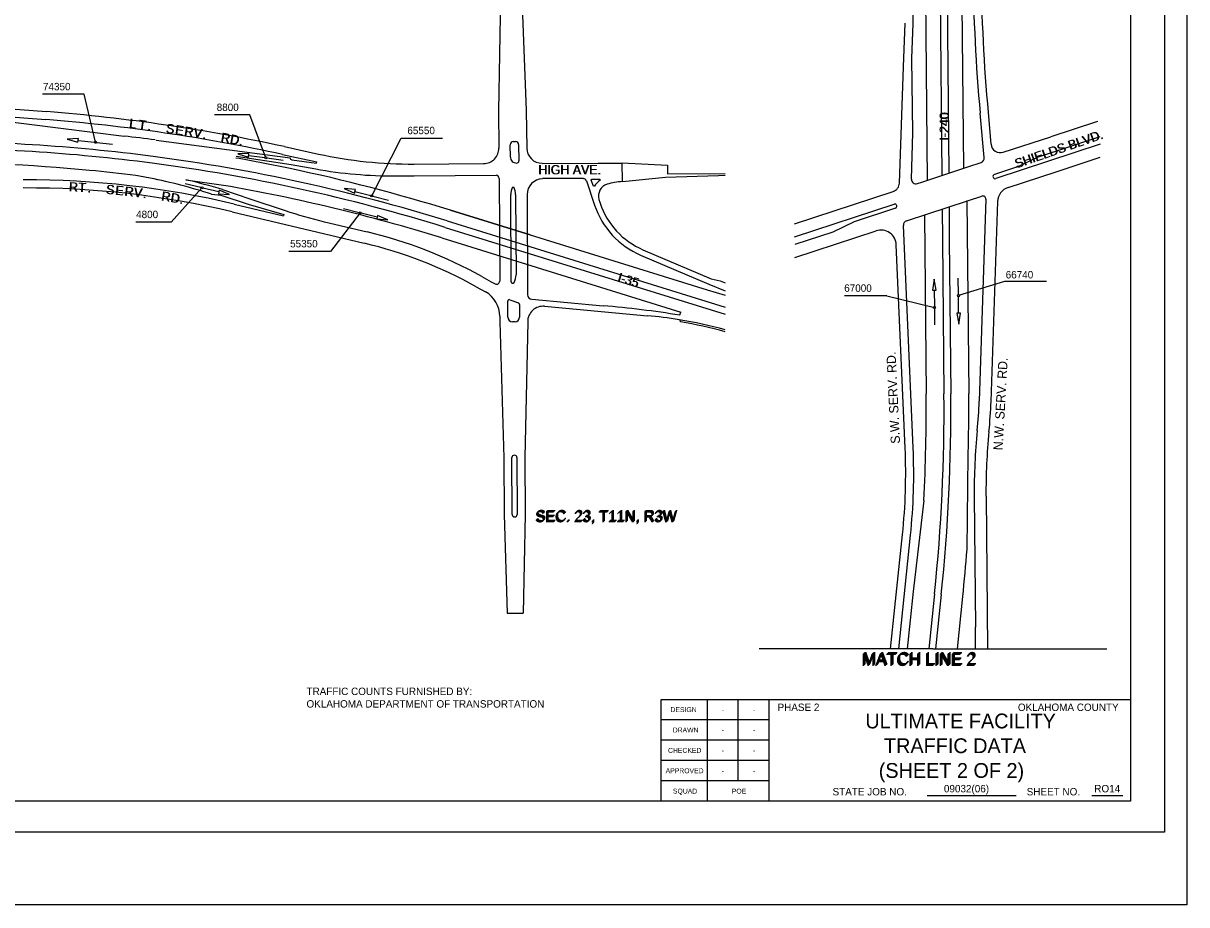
# Model space of a CAD drawing. Extents: x 143344 to 150544, y -2153266 to -2148466.
# Drawn here: x 146776 to 150544, y -2153266 to -2150410 of the extents above; entities that cross this region are included whole.
import ezdxf

# ---------------------------------------------------------------- set-up
doc = ezdxf.new("R2010")
doc.units = 0
for name, color, linetype in [('4', 7, 'Continuous'), ('5', 7, 'Continuous'), ('6', 7, 'Continuous'), ('EXIST', 7, 'Continuous'), ('EXPAV', 7, 'Continuous'), ('PH1a-PR-I240', 7, 'Continuous'), ('PH1a-PR-ServRd', 7, 'Continuous'), ('PROP', 7, 'Continuous'), ('SHT_Plot_Shape_Full', 7, 'Continuous'), ('SHT_Plot_Shape_Half', 7, 'Continuous'), ('SHT_Sheet_Border', 7, 'Continuous'), ('SHT_Standard_Sheet_Lines', 7, 'Continuous'), ('SHT_Standard_Sheet_Txt', 7, 'Continuous'), ('T', 7, 'Continuous')]:
    doc.layers.add(name, color=color, linetype=linetype)

# ---------------------------------------------------------------- blocks, each defined once
blk = doc.blocks.new('ARR')
at = {"layer": '6'}
for p, q in [((134.5, 0), (0, 0)), ((285.8, 0), (151.3, 0))]:
    blk.add_line(p, q, dxfattribs=at)
blk.add_lwpolyline([(285.8, 15.2), (285.8, -15.2), (377.2, 0)], close=True, dxfattribs=at)
blk.add_circle((142.9, 0), 8.42, dxfattribs=at)

msp = doc.modelspace()

# ---------------------------------------------------------------- linework, layer by layer
at = {"layer": '4'}
for q in [(149159.4, -2152436.2), (150285.6, -2152436.2)]:
    msp.add_line((149722.5, -2152436.2), q, dxfattribs=at)
at = {"layer": '6'}
for p, q in [((146972.9, -2150640.1), (146838, -2150640.1)), ((147009.6, -2150795.6), (146972.9, -2150640.1)), ((146972.9, -2150640.1), (146972.9, -2150640.1)), ((147509.3, -2150707.1), (147395.5, -2150707.1)), ((147561.9, -2150845.4), (147509.3, -2150707.1)), ((147509.3, -2150707.1), (147509.3, -2150707.1)), ((147904.5, -2150968.9), (148000.3, -2150782.2)), ((148000.3, -2150782.2), (148000.3, -2150782.2)), ((148000.3, -2150782.2), (148133.6, -2150782.2)), ((147354.8, -2150943.2), (147254.8, -2151054.2)), ((147867.5, -2151024.5), (147771.5, -2151148.9)), ((147254.8, -2151054.2), (147141, -2151054.2)), ((147254.8, -2151054.2), (147254.8, -2151054.2)), ((147771.5, -2151148.9), (147635.8, -2151148.9)), ((147771.5, -2151148.9), (147771.5, -2151148.9)), ((149954.3, -2151246.4), (149804.9, -2151292.4)), ((150090.5, -2151246.4), (149954.3, -2151246.4)), ((149572.6, -2151292.8), (149436.4, -2151292.8)), ((149572.6, -2151292.8), (149726.9, -2151331.1))]:
    msp.add_line(p, q, dxfattribs=at)
at = {"layer": 'EXIST'}
for p, q in [((146656.1, -2150681), (146851.2, -2150696.3)), ((146631.6, -2150715.7), (147102.9, -2150775.7)), ((146653.9, -2150706.9), (146849.2, -2150722.2))]:
    msp.add_line(p, q, dxfattribs=at)
for centre, radius, start, end in [((146449, -2156533.3), 5794.6, 82.52117, 83.52117), ((146449, -2156533.3), 5740.6, 82.52117, 90.35541), ((146449, -2156533.3), 5718.6, 82.5212, 90.3554), ((146449, -2156533.3), 5672.6, 84.5212, 90.3555), ((146449, -2156533.3), 5672.6, 82.9934, 84.5212), ((146809.2, -2152777.8), 1903.9, 78.5556, 79.965)]:
    msp.add_arc(centre, radius, start, end, dxfattribs=at)
at = {"layer": 'EXPAV'}
for p, q in [((148329.1, -2149864.1), (148315.2, -2150693.8)), ((148374.1, -2149923), (148405.2, -2150692.7)), ((148315.2, -2150693.8), (148316.6, -2150814.1)), ((148405.2, -2150692.7), (148406.6, -2150814.1)), ((150255.6, -2150728), (150104.5, -2150777.6)), ((149949.7, -2150827.6), (150104.5, -2150777.6)), ((150060.9, -2150843.5), (150264.2, -2150776.8)), ((147206.7, -2150788.5), (147640.3, -2150845.7)), ((147621.6, -2150809.7), (147732.3, -2150833.7)), ((148353.9, -2150843.3), (148353.4, -2150803.3)), ((148363.3, -2150793.2), (148370.3, -2150793.1)), ((148380.4, -2150803), (148381.1, -2150856)), ((150264.2, -2150802.1), (149925.9, -2150913.1)), ((147465.5, -2150840.7), (147643.5, -2150867.3)), ((147616.1, -2150835.1), (147726.3, -2150859)), ((147645.4, -2150852.4), (147725.6, -2150863)), ((149992.8, -2150876.4), (150060.9, -2150843.5)), ((150121.8, -2150890.9), (150264.1, -2150844.2)), ((147643.5, -2150867.3), (147723.1, -2150881.8)), ((147725.6, -2150863), (147726.3, -2150859)), ((148042.1, -2150866), (148266.9, -2150864.7)), ((148456.9, -2150864.7), (148637.3, -2150863.6)), ((148637.3, -2150863.6), (148716.3, -2150863.1)), ((148715.1, -2150861.9), (148715.5, -2150923.1)), ((148716.3, -2150861.9), (148862.3, -2150869.5)), ((148862.3, -2150869.5), (148862.5, -2150897.6)), ((149992.8, -2150876.4), (149921.5, -2150899.8)), ((149966.1, -2150942), (150121.8, -2150890.9)), ((147302.2, -2150917.2), (147424.4, -2150935)), ((147302.2, -2150917.2), (147424.4, -2150935)), ((147981.6, -2150904.4), (148042.4, -2150904)), ((148042.4, -2150904), (148307.5, -2150902.5)), ((148317.6, -2150912.4), (148319.1, -2151245.3)), ((148590.6, -2150912.5), (148457.5, -2150913.3)), ((148600.1, -2150920.5), (148626.4, -2150999.1)), ((148615.2, -2150918.3), (148617, -2150915.5)), ((148622.6, -2150937.3), (148615.2, -2150918.3)), ((148617, -2150915.5), (148643.4, -2150914.7)), ((148643.4, -2150914.7), (148644.6, -2150918.4)), ((148716.7, -2150923.1), (148856.6, -2150908.2)), ((148856.6, -2150908.2), (149027.6, -2150902.9)), ((148862.5, -2150897.6), (149048.9, -2150896.4)), ((149027.6, -2150902.9), (149048.9, -2150902.3)), ((147385.3, -2150963.2), (147415.6, -2150966.8)), ((147415.6, -2150966.8), (147504.1, -2150996.4)), ((147421.7, -2150948.8), (147510.1, -2150978.4)), ((148356, -2151240), (148354.8, -2150965)), ((148360.9, -2150940.8), (148364.4, -2150940.7)), ((148370.8, -2150964.9), (148372, -2151224.9)), ((148407.8, -2150964.8), (148409.3, -2151289.2)), ((148626.2, -2150937.6), (148622.6, -2150937.3)), ((149273.9, -2151059.8), (149593.2, -2150955)), ((147458.7, -2150995.6), (147618.3, -2151033.6)), ((147504.1, -2150996.4), (147619.4, -2151029.7)), ((147510.1, -2150978.4), (147623.8, -2151016.4)), ((149274.3, -2151101.8), (149596.3, -2150996.1)), ((147452.7, -2151020.9), (147880.6, -2151122.7)), ((147619.4, -2151029.7), (147618.3, -2151033.6)), ((148417.5, -2151095.8), (148159.8, -2151015.9)), ((148159.8, -2151015.9), (148417.5, -2151095.8)), ((149600.7, -2151009.4), (149466.7, -2151053.4)), ((147751.1, -2151052.8), (147889.4, -2151085.7)), ((148142.6, -2151071.3), (149048.9, -2151352.3)), ((148149.2, -2151050.2), (149048.9, -2151329.2)), ((149274.9, -2151169), (149538.1, -2151082.6)), ((149466.7, -2151053.4), (149398.6, -2151086.3)), ((148132, -2151105.6), (148905.4, -2151345.4)), ((148417.5, -2151095.8), (148990.6, -2151273.5)), ((149398.6, -2151086.3), (149274.5, -2151127)), ((148782.9, -2151143.5), (149003.7, -2151238.2)), ((148775.4, -2151160.9), (148996.2, -2151255.6)), ((148261.2, -2151230.2), (148291.8, -2151247.2)), ((148242.7, -2151263.4), (148273.4, -2151280.4)), ((148291.8, -2151247.2), (148304.2, -2151254.1)), ((148356.1, -2151247.4), (148356, -2151240)), ((148996.2, -2151255.6), (149048.9, -2151276.4)), ((149003.7, -2151238.2), (149033, -2151244.3)), ((149033, -2151244.3), (149048.9, -2151251.1)), ((148352.1, -2151305.6), (148380.2, -2151316.2)), ((148422.9, -2151304), (148654.1, -2151325.2)), ((148990.6, -2151273.5), (149048.9, -2151291)), ((148345.6, -2151362.2), (148345.4, -2151310.3)), ((148383.4, -2151320.8), (148383.6, -2151362)), ((148464.2, -2151326.9), (148797.7, -2151357.4)), ((148902.4, -2151355), (148905.4, -2151345.4)), ((148319.6, -2151358.7), (148319.7, -2151377.3)), ((148319.7, -2151377.3), (148332.7, -2151817.3)), ((148368.7, -2151377.1), (148360.7, -2151377.1)), ((148409.7, -2151376.9), (148400.7, -2151816.9)), ((148332.7, -2151817.3), (148333.5, -2152001.4)), ((148359.5, -2152001.3), (148358.7, -2151817.1)), ((148374.7, -2151817.1), (148375.5, -2152001.2)), ((148400.7, -2151816.9), (148401.5, -2152001.1)), ((148333.5, -2152001.4), (148342.9, -2152321.4)), ((148401.5, -2152001.1), (148394.9, -2152321.1)), ((148342.9, -2152321.4), (148394.9, -2152321.1))]:
    msp.add_line(p, q, dxfattribs=at)
for centre, radius, start, end in [((146402.4, -2156421.3), 5742.6, 77.74204, 85.51732), ((146402.4, -2156421.3), 5716.6, 77.742, 85.5173), ((148266.6, -2150814.7), 50, 270.3443, 0.672), ((148363.4, -2150803.2), 10, 90.672, 180.672), ((148370.4, -2150803.1), 10, 0.672, 90.672), ((148456.6, -2150813.5), 50, 180.672, 270.3596), ((146449, -2156533.3), 5740.6, 72.77283, 82.52117), ((146449, -2156533.3), 5776.6, 78.09426, 79.87617), ((147646.2, -2150846.4), 6, 172.4865, 262.4865), ((148033.6, -2149446.7), 1419.4, 257.742, 270.3443), ((148373.9, -2150843), 20, 180.672, 270.672), ((148374.1, -2150856), 7, 270.672, 0.672), ((146449, -2156533.3), 5718.6, 72.7728, 82.5212), ((146449, -2156533.3), 5776.6, 72.77283, 78.09426), ((147973.2, -2149511.7), 1392.7, 259.6534, 270.3443), ((146793.1, -2153795.4), 2877.8, 76.627, 90.3443), ((146809.2, -2152777.8), 1903.9, 72.3873, 78.5556), ((146929, -2152569), 1693.5, 73.0874, 77.2684), ((148307.6, -2150912.5), 10, 0.2591, 90.3443), ((148457.8, -2150964.5), 50, 90.3596, 180.2591), ((148590.6, -2150923.7), 10, 18.5091, 90.3596), ((148679.1, -2150969.8), 62, 123.9003, 148.6868), ((148679.1, -2150969.8), 40, 107.9501, 195.4962), ((148722.3, -2151103), 180, 91.7917, 107.9501), ((149923.7, -2150906.5), 7, 108.1765, 288.1765), ((146793.1, -2153795.4), 2851.8, 76.627, 90.3443), ((146449, -2156533.3), 5682.6, 72.7728, 80.1169), ((148404.8, -2150964.8), 50, 151.3041, 180.2591), ((148320.8, -2150965.1), 50, 0.2591, 29.2142), ((148881.5, -2150913.7), 269, 198.5091, 246.7728), ((148881.5, -2150913.7), 250, 195.4962, 198.5091), ((148881.5, -2150913.7), 250, 198.5091, 246.7728), ((149598.5, -2151002.7), 7, 288.1765, 108.1765), ((148092.5, -2149616.6), 1476.3, 251.4873, 256.627), ((147552.3, -2152503.6), 1457.4, 60.8964, 76.627), ((147552.3, -2152503.6), 1419.4, 60.8964, 76.627), ((148322, -2151225.1), 50, 330.3327, 0.2591), ((148309.1, -2151245.4), 10, 240.8964, 0.2591), ((148309.1, -2151245.4), 10, 240.8964, 0.2591), ((148361.1, -2151247.4), 5, 180.2591, 330.3327), ((148229.6, -2151359.1), 90, 0.2591, 60.8964), ((148229.6, -2151359.1), 90, 0.2591, 60.8964), ((148350.4, -2151310.3), 5, 69.3317, 180.2591), ((148424.3, -2151289.1), 15, 180.2591, 264.7728), ((148378.4, -2151320.9), 5, 0.2591, 69.3317), ((148459.7, -2151376.7), 50, 84.7728, 180.2591), ((148354.6, -2154789.9), 3477.7, 80.9383, 85.058), ((148360.6, -2151362.1), 15, 180.2591, 270.2591), ((148368.6, -2151362.1), 15, 270.2591, 0.2591), ((148667.2, -2152783.8), 1432.4, 80.6518, 84.7728), ((148667.2, -2152783.8), 1432.4, 74.5431, 80.6518), ((148898.9, -2151376.4), 6, 350.5306, 80.6518), ((148667.2, -2152783.8), 1426.4, 74.4765, 80.4108), ((148366.7, -2151817.1), 8, 0.2591, 180.2591), ((148367.5, -2152001.2), 8, 180.2591, 0.2591)]:
    msp.add_arc(centre, radius, start, end, dxfattribs=at)
at = {"layer": 'PH1a-PR-I240'}
for p, q in [((149739.6, -2149656.7), (149751.4, -2150903)), ((149764.4, -2149956.5), (149773.3, -2150895.8)), ((149695.4, -2150053.8), (149703.6, -2150918.9)), ((149816.2, -2150349.3), (149821.2, -2150879.9))]:
    msp.add_line(p, q, dxfattribs=at)
at = {"layer": 'PH1a-PR-ServRd'}
for p, q in [((149627.1, -2150551.3), (149632, -2150410)), ((149654, -2150524.4), (149658, -2150410.9)), ((149613.9, -2150927.7), (149627.1, -2150551.3)), ((149657.6, -2150764.7), (149654, -2150524.4)), ((149888.2, -2150845.3), (149875.2, -2150701.7)), ((149901.1, -2150699.4), (149910.4, -2150801.8)), ((149652.4, -2150914.6), (149657.6, -2150764.7)), ((149686.7, -2150924.5), (149838.4, -2150874.1)), ((149838.4, -2150874.1), (149878.1, -2150860.8)), ((149672.1, -2150929.3), (149686.7, -2150924.5))]:
    msp.add_line(p, q, dxfattribs=at)
for centre, radius, start, end in [((145827.6, -2150277.4), 3832.7, 358.0035, 0.5432), ((155607.4, -2150183.4), 5755.6, 180.54316, 185.16665), ((155607.4, -2150183.4), 5729.6, 180.54316, 185.16665), ((149940.3, -2150799.1), 30, 185.1667, 288.3841), ((149873.3, -2150846.6), 15, 288.5888, 5.1667), ((149584, -2150926.6), 30, 287.9834, 358.0035), ((149667.4, -2150915.1), 15, 178.0035, 288.1765)]:
    msp.add_arc(centre, radius, start, end, dxfattribs=at)
at = {"layer": 'PROP'}
for p, q in [((149837.9, -2150984.1), (149880.8, -2150970)), ((149637.2, -2151050), (149837.9, -2150984.1)), ((149774.4, -2151005), (149775.4, -2151110.1)), ((149832.2, -2150984.2), (149838.1, -2151609.5)), ((149893.9, -2150979.9), (149872.4, -2151633.8)), ((149931.7, -2150987.9), (149910.4, -2151635)), ((149694.6, -2151031.2), (149700.1, -2151610.8)), ((149752.4, -2151012.2), (149753.4, -2151110.3)), ((149658.3, -2151785.6), (149626.9, -2151064.9)), ((149753.4, -2151110.3), (149758.1, -2151610.3)), ((149775.4, -2151110.1), (149780.1, -2151610.1)), ((149632.3, -2151786.7), (149603.6, -2151127.9)), ((149833, -2152113.6), (149836.6, -2151809.7)), ((149856.3, -2151942.2), (149860.3, -2152366.4)), ((149894.3, -2151941.8), (149898.9, -2152436.2)), ((149692.9, -2151956.1), (149657.9, -2152250.5)), ((149585.2, -2152436.2), (149623.8, -2152066.1)), ((149611.4, -2152436.2), (149649.7, -2152068.8)), ((149657.9, -2152250.5), (149638.5, -2152436.2)), ((149727.5, -2152257.9), (149708.9, -2152436.2)), ((149749.4, -2152260.1), (149731, -2152436.2)), ((149801.4, -2152436.2), (149819, -2152267.4))]:
    msp.add_line(p, q, dxfattribs=at)
for centre, radius, start, end in [((149883.9, -2150979.5), 10, 358.1141, 108.1765), ((149981.6, -2150989.5), 50, 108.1324, 178.1141), ((149553.7, -2151130.1), 50, 2.4929, 108.1765), ((149641.9, -2151064.3), 15, 108.1765, 182.4929), ((144039.8, -2151664.5), 5718.6, 354.0443, 0.5432), ((144039.8, -2151664.5), 5740.6, 354.04429, 0.54316), ((144039.8, -2151664.5), 5798.6, 358.56495, 0.54316), ((144039.8, -2151664.5), 5660.6, 357.0477, 0.5432), ((148465.8, -2151587.5), 1407.4, 354.2235, 358.1141), ((148465.8, -2151587.5), 1445.4, 354.2235, 358.1141), ((151791, -2151923.9), 1934.9, 174.2235, 180.5432), ((151791, -2151923.9), 1896.9, 174.2235, 180.5432), ((147737.2, -2151869.2), 1896.9, 354.0443, 2.4929), ((147737.2, -2151869.2), 1922.9, 354.0443, 2.4929), ((144039.8, -2151664.5), 5810.6, 354.04429, 355.56753), ((146995.6, -2152393.6), 2864.8, 359.1474, 0.5432)]:
    msp.add_arc(centre, radius, start, end, dxfattribs=at)
at = {"layer": 'SHT_Plot_Shape_Full'}
msp.add_lwpolyline([(143344.4, -2148465.6), (150544.4, -2148465.6), (150544.4, -2153265.6), (143344.4, -2153265.6)], close=True, dxfattribs=at)
at = {"layer": 'SHT_Plot_Shape_Half'}
msp.add_lwpolyline([(143671.9, -2148630.6), (150471.9, -2148630.6), (150471.9, -2153030.6), (143671.9, -2153030.6)], close=True, dxfattribs=at)
at = {"layer": 'SHT_Sheet_Border'}
for p, q in [((148841.9, -2152930.6), (148841.9, -2152600.6)), ((148841.9, -2152600.6), (150361.9, -2152600.6)), ((149191.9, -2152930.6), (149191.9, -2152600.4))]:
    msp.add_line(p, q, dxfattribs=at)
msp.add_lwpolyline([(150361.9, -2152930.6), (144061.9, -2152930.6), (144061.9, -2148730.6), (150361.9, -2148730.6)], close=True, dxfattribs=at)
at = {"layer": 'SHT_Standard_Sheet_Lines'}
for p, q in [((148991.9, -2152930.6), (148991.9, -2152600.4)), ((149091.9, -2152864.6), (149091.9, -2152600.4)), ((149704, -2152911.4), (149992.1, -2152911.4)), ((150237, -2152911.4), (150337.5, -2152911.4))]:
    msp.add_line(p, q, dxfattribs=at)
for points in [[(149191.9, -2152666.6), (148841.9, -2152666.6)], [(149191.9, -2152732.6), (148841.9, -2152732.6)], [(149191.9, -2152798.6), (148841.9, -2152798.6)], [(149191.9, -2152864.6), (148841.9, -2152864.6)]]:
    msp.add_lwpolyline(points, dxfattribs=at)

# ---------------------------------------------------------------- block references
at = {"layer": '4', "xscale": 0.3937000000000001}
for p, yscale, rotation in [((149727.4, -2151387.3), 0.3937000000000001, 90.5079954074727), ((149804.2, -2151236.2), 0.39369999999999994, -89.27250306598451)]:
    msp.add_blockref('ARR', p, dxfattribs=dict(at, yscale=yscale, rotation=rotation))
at = {"layer": '6'}
for p, xscale, yscale, rotation in [((147065.5, -2150801.8), 0.3937000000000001, 0.39370000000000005, 173.69557578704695), ((147617.6, -2150853.1), 0.3937, 0.3937, 172.20636568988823), ((147300.1, -2150930), 0.3937000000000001, 0.39370000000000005, -13.565007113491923), ((147958.9, -2150983.2), 0.39370000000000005, 0.3937000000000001, 165.32215268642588), ((147812.9, -2151010.9), 0.39370000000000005, 0.3937000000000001, -14.021492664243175)]:
    msp.add_blockref('ARR', p, dxfattribs=dict(at, xscale=xscale, yscale=yscale, rotation=rotation))

# ---------------------------------------------------------------- texts
at = {"layer": '5'}
for s, rotation, p in [('I-240', 90, (149773.9, -2150788.9)), ('I-240', 90, (149773.9, -2150790.9)), ('L', 352.8628, (147117.1, -2150748.3)), ('L', 352.8628, (147119.1, -2150748.5)), ('T', 352.5613, (147146.9, -2150752.1)), ('T', 352.5613, (147148.9, -2150752.3)), ('S', 351.6567, (147236.1, -2150764.4)), ('S', 351.6567, (147238, -2150764.7)), ('E', 351.3551, (147265.7, -2150768.9)), ('E', 351.3551, (147267.7, -2150769.2)), ('.', 352.2598, (147176.6, -2150756)), ('.', 352.2598, (147178.6, -2150756.3)), ('R', 351.0536, (147295.4, -2150773.4)), ('R', 351.0536, (147297.3, -2150773.8)), ('V', 350.7521, (147325, -2150778.2)), ('V', 350.7521, (147327, -2150778.5)), ('.', 350.4505, (147354.6, -2150783.1)), ('.', 350.4505, (147356.6, -2150783.4)), ('R', 349.8475, (147413.7, -2150793.3)), ('R', 349.8475, (147415.7, -2150793.7)), ('D', 349.5459, (147443.2, -2150798.7)), ('D', 349.5459, (147445.2, -2150799.1)), ('SHIELDS BLVD.', 19.0494, (149992.9, -2150880.6)), ('SHIELDS BLVD.', 19.0494, (149994.8, -2150880)), ('.', 349.2444, (147472.7, -2150804.2)), ('.', 349.2444, (147474.7, -2150804.6)), ('R', 357.3948, (146922.7, -2150954.5)), ('R', 357.3948, (146924.7, -2150954.6)), ('T', 356.7922, (146952.7, -2150956.1)), ('T', 356.7922, (146954.7, -2150956.2)), ('.', 356.1895, (146982.6, -2150957.9)), ('.', 356.1895, (146984.6, -2150958)), ('S', 354.9842, (147042.5, -2150962.5)), ('S', 354.9842, (147044.5, -2150962.7)), ('E', 354.3816, (147072.3, -2150965.3)), ('E', 354.3816, (147074.3, -2150965.5)), ('R', 353.7789, (147102.2, -2150968.4)), ('R', 353.7789, (147104.2, -2150968.6)), ('V', 353.1763, (147132, -2150971.8)), ('V', 353.1763, (147134, -2150972)), ('R', 351.3683, (147221.2, -2150983.9)), ('R', 351.3683, (147223.1, -2150984.2)), ('D', 350.7657, (147250.8, -2150988.6)), ('D', 350.7657, (147252.8, -2150988.9)), ('.', 352.5736, (147161.7, -2150975.5)), ('.', 352.5736, (147163.7, -2150975.8)), ('.', 350.163, (147280.4, -2150993.5)), ('.', 350.163, (147282.4, -2150993.9)), ('I-35', 342.7222, (148698.1, -2151245.8)), ('I-35', 342.7222, (148700, -2151246.4)), ('S.W. SERV. RD.', 92.7981, (149615.9, -2151771.4)), ('N.W. SERV. RD.', 86.839, (149948, -2151794.1))]:
    msp.add_text(s, height=30, rotation=rotation, dxfattribs=at).set_placement(p)
for s, height, p in [('HIGH AVE.', 30, (148443.5, -2150899.4)), ('HIGH AVE.', 30, (148445.5, -2150899.4)), ('SEC. 23, T11N, R3W', 36, (148436.1, -2152023.9)), ('SEC. 23, T11N, R3W', 36, (148437.6, -2152022.3)), ('SEC. 23, T11N, R3W', 36, (148432.9, -2152027)), ('SEC. 23, T11N, R3W', 36, (148434.5, -2152025.4))]:
    msp.add_text(s, height=height, dxfattribs=at).set_placement(p)
at = {"layer": 'SHT_Standard_Sheet_Txt'}
for s, height, p in [('DESIGN', 16, (148872.3, -2152641.5)), ('OKLAHOMA COUNTY', 24, (149997.5, -2152637.9)), ('-', 16, (149038, -2152641.5)), ('-', 16, (149139.6, -2152641.5)), ('ULTIMATE FACILITY', 48, (149503.5, -2152694.3)), ('DRAWN', 16, (148879.5, -2152707.5)), ('-', 16, (149038, -2152707.5)), ('-', 16, (149139.6, -2152707.5)), ('TRAFFIC DATA', 48, (149563.8, -2152774.5)), ('CHECKED', 16, (148864.4, -2152773.5)), ('-', 16, (149038, -2152773.6)), ('-', 16, (149139.6, -2152773.6)), ('(SHEET 2 OF 2)', 48, (149546.9, -2152854.6)), ('APPROVED', 16, (148856.6, -2152839.5)), ('-', 16, (149038, -2152839.6)), ('-', 16, (149139.6, -2152839.6)), ('SQUAD', 16, (148880.2, -2152905.5)), ('POE', 16, (149070.9, -2152905.6)), ('STATE JOB NO.', 24, (149397.3, -2152911.4)), ('09032(06)', 24, (149757.9, -2152901.5)), ('SHEET NO. ', 24, (150026, -2152911.4)), ('RO14', 24, (150245, -2152901.5))]:
    msp.add_text(s, height=height, dxfattribs=at).set_placement(p)
msp.add_text('PHASE 2', height=24, rotation=0, dxfattribs=at).set_placement((149219, -2152637.9))
at = {"layer": 'T'}
for s, height, p in [('74350', 24, (146839.8, -2150627.1)), ('8800', 24, (147402.5, -2150694.2)), ('65550', 24, (148020, -2150769.3)), ('4800', 24, (147141.4, -2151041.3)), ('55350', 24, (147640.3, -2151136)), ('66740', 24, (149958, -2151236.7)), ('67000', 24, (149435, -2151279.9)), ('MATCH LINE 2', 40, (149490.1, -2152492.2)), ('MATCH LINE 2', 40, (149492, -2152490.4)), ('MATCH LINE 2', 40, (149493.8, -2152488.6)), ('MATCH LINE 2', 40, (149495.7, -2152486.7)), ('TRAFFIC COUNTS FURNISHED BY:', 24, (147693.3, -2152586.3)), ('OKLAHOMA DEPARTMENT OF TRANSPORTATION', 24, (147693.3, -2152626.9))]:
    msp.add_text(s, height=height, dxfattribs=at).set_placement(p)

doc.saveas('drawing.dxf')
